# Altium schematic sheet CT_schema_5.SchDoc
size 218 x 258 mm
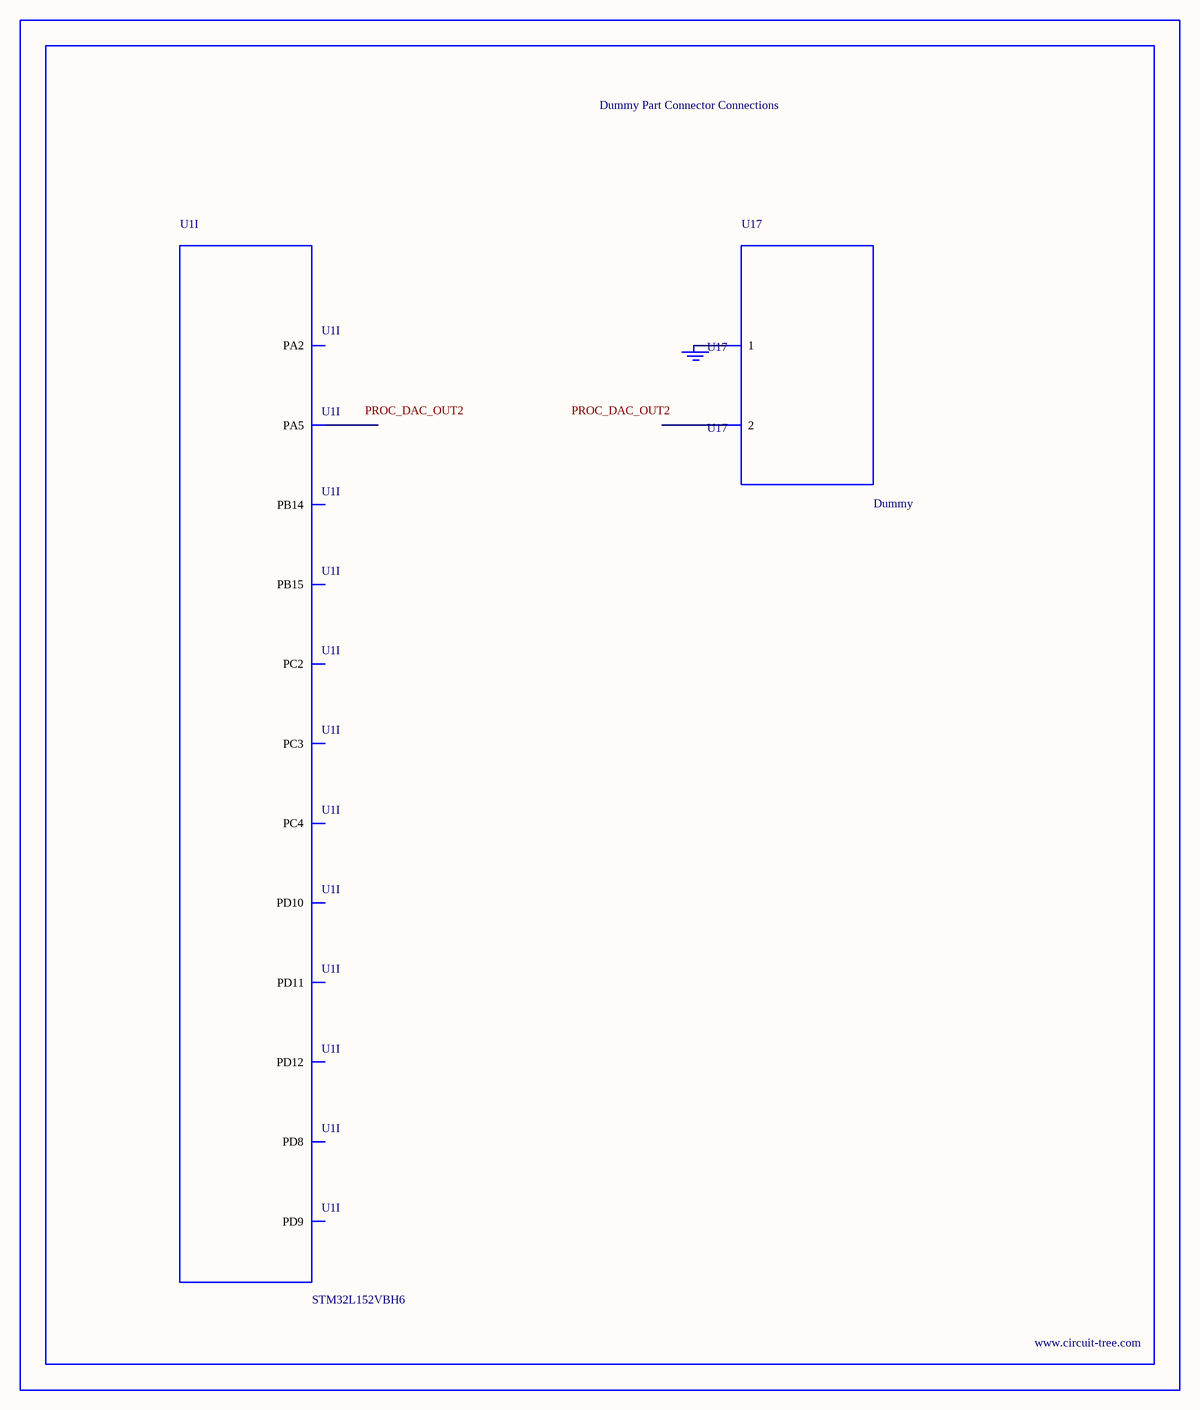
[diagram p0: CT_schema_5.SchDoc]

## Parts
BORDER4  (no value)
GND_INSTANCE_4_0  (no value)
U1  STM32L152VBH6  [UFBGA100]  (part I of 9)
U17  Dummy  [DUMMY_PACKAGE_135]

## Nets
NetGND_INSTANCE_4_0_0: GND_INSTANCE_4_0.0(GND) U17.1

Not connected (* = marked no-connect by the designer): U1 J3(PC2) J10(PD12) J11(PD11) J12(PD10) K2(PC3) K3(PA2) K4(PA5) K5(PC4) K8(PD9) K9(PD8) K10(PB15) K11(PB14); U17 2

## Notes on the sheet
- Labels drawn without touching a wire or pin: PROC_DAC_OUT2

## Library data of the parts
BORDER4 = BORDER_PAGE4
GND_INSTANCE_4_0 = GND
